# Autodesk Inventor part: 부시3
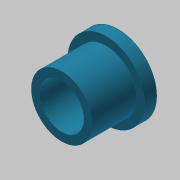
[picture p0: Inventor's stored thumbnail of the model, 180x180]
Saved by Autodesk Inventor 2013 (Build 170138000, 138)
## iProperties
Created: 2020-03
Part Number: 부시3
Material: 스테인리스강
Document SubType Name: Modeling
Designer: mduedu
Density: 1 g/cm^3
Author: mduedu
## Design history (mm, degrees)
sketch "스케치1"
  geometry: L1 (0, 0)-(11, 0); L2 (11, 0)-(11, 7.5); L3 (11, 7.5)-(0, 7.5); L4 (0, 7.5)-(0, 0); L5 (11, 0)-(14, 0); L6 (14, 0)-(14, 9.5); L7 (14, 9.5)-(11, 9.5); L8 (11, 9.5)-(11, 0)
  constraints: 16 end point, 4 parallel, 2 horizontal, 2 perpendicular
  dimensions: "d0" = 14 distance between parallel lines of L6 L4; "d2" = 15 diameter of L3 L1; "d3" = 19 diameter of L7 L5; "d4" = 3 distance of L6.end L7.end
revolve "회전1" sketch "스케치1" stored, may be unused: angle "d5" = 90 deg
hole "구멍1" diameter "d8" = 11; stored, may be unused: countersink angle "d12" = 90 deg, drill point angle "d14" = 118 deg; dims "d9" = 6, "d10" = 4, "d11" = 2, "d13" = 8, "d15" = 10, "d16" = 10
node "솔리드1"
